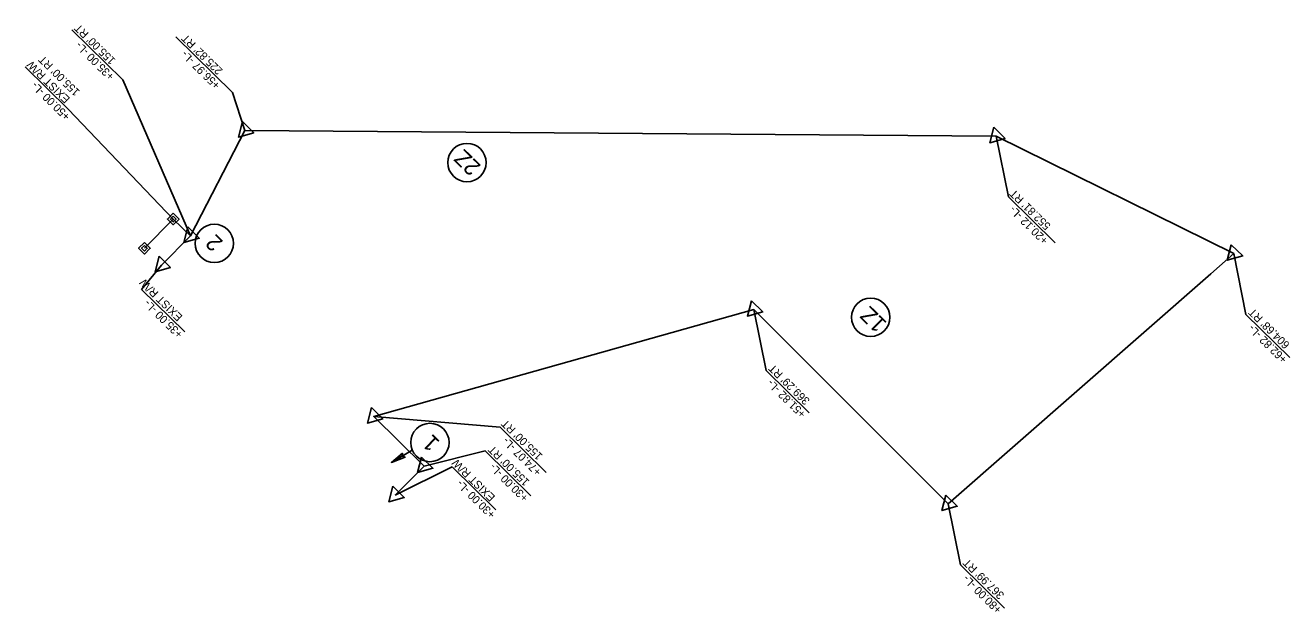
# Model space of a CAD drawing. Extents: x 1266020 to 1268272, y 771352 to 772865.
# Drawn here: x 1267482 to 1268272, y 771352 to 771719 of the extents above; entities that cross this region are included whole.
import ezdxf

# ---------------------------------------------------------------- set-up
doc = ezdxf.new("R2010")
doc.units = 0
for name, color, linetype in [('Prop Dimension Text', 7, 'Continuous'), ('Prop Easement Permanent Drainage', 7, 'Continuous'), ('Prop Easement Permanent Drainage Station Offsets', 7, 'Continuous'), ('Prop Parcel Number CELL', 7, 'Continuous'), ('Prop Parcel Number Text', 7, 'Continuous'), ('Prop ROW Marker CELL', 7, 'Continuous'), ('Prop ROW Permanent Easement CELL', 7, 'Continuous'), ('Prop ROW RW Lines', 7, 'Continuous'), ('Prop ROW Station Offsets', 7, 'Continuous')]:
    doc.layers.add(name, color=color, linetype=linetype)

msp = doc.modelspace()

# ---------------------------------------------------------------- linework, layer by layer
at = {"layer": 'Prop Dimension Text'}
msp.add_lwpolyline([(1267717.81, 771451.44), (1267710.87, 771445.51), (1267719.46, 771448.75), (1267717.66, 771449.54)], close=True, dxfattribs=at)
at = {"layer": 'Prop Easement Permanent Drainage'}
msp.add_lwpolyline([(1267585.27, 771587.19), (1267574.58, 771597.72), (1267556.57, 771579.44)], dxfattribs=at)
at = {"layer": 'Prop Easement Permanent Drainage Station Offsets'}
for p, q in [((1267482.14, 771692.95), (1267509.22, 771666.27)), ((1267509.22, 771666.27), (1267574.58, 771597.72))]:
    msp.add_line(p, q, dxfattribs=at)
at = {"layer": 'Prop Parcel Number CELL'}
for p, q in [((1267758.1, 771633.03), (1267758.1, 771633.03)), ((1267600.22, 771582.5), (1267600.22, 771582.5)), ((1268010.38, 771536.27), (1268010.38, 771536.27)), ((1267723.94, 771453.27), (1267710.87, 771445.51)), ((1267734.96, 771458.02), (1267734.96, 771458.02))]:
    msp.add_line(p, q, dxfattribs=at)
for centre in [(1267758.1, 771633.03), (1267600.22, 771582.5), (1268010.38, 771536.27), (1267734.96, 771458.02)]:
    msp.add_circle(centre, 12, dxfattribs=at)
at = {"layer": 'Prop ROW Marker CELL'}
for p, q in [((1267619.32, 771653.06), (1267619.32, 771653.06)), ((1268088.77, 771649.56), (1268088.77, 771649.56)), ((1267585.27, 771587.19), (1267585.27, 771587.19)), ((1268237.22, 771576.11), (1268237.22, 771576.11)), ((1267567.26, 771568.92), (1267567.26, 771568.92)), ((1267937.38, 771541.08), (1267937.38, 771541.08)), ((1267699.9, 771474.24), (1267699.9, 771474.24)), ((1267731.29, 771443.31), (1267731.29, 771443.31)), ((1267713.31, 771425.06), (1267713.31, 771425.06)), ((1268058.86, 771419.57), (1268058.86, 771419.57))]:
    msp.add_line(p, q, dxfattribs=at)
for points in [[(1267617.78, 771658.62), (1267624.9, 771651.63), (1267615.29, 771648.94)], [(1268087.23, 771655.12), (1268094.35, 771648.12), (1268084.73, 771645.43)], [(1267583.72, 771592.75), (1267590.84, 771585.75), (1267581.23, 771583.07)], [(1268235.68, 771581.67), (1268242.8, 771574.67), (1268233.18, 771571.99)], [(1267565.72, 771574.48), (1267572.84, 771567.48), (1267563.23, 771564.79)], [(1267935.84, 771546.64), (1267942.96, 771539.65), (1267933.34, 771536.96)], [(1267698.36, 771479.8), (1267705.48, 771472.8), (1267695.87, 771470.11)], [(1267729.75, 771448.87), (1267736.87, 771441.87), (1267727.26, 771439.19)], [(1267711.77, 771430.62), (1267718.89, 771423.62), (1267709.27, 771420.94)], [(1268057.32, 771425.13), (1268064.44, 771418.13), (1268054.82, 771415.44)]]:
    msp.add_lwpolyline(points, close=True, dxfattribs=at)
at = {"layer": 'Prop ROW Permanent Easement CELL'}
for p, q in [((1267574.58, 771597.72), (1267574.58, 771597.72)), ((1267556.57, 771579.44), (1267556.57, 771579.44))]:
    msp.add_line(p, q, dxfattribs=at)
for points in [[(1267574.58, 771601.32), (1267578.18, 771597.72), (1267574.58, 771594.12), (1267570.98, 771597.72)], [(1267574.58, 771599.52), (1267576.38, 771597.72), (1267574.58, 771595.92), (1267572.78, 771597.72)], [(1267556.57, 771583.04), (1267560.17, 771579.44), (1267556.57, 771575.84), (1267552.97, 771579.44)], [(1267556.57, 771581.24), (1267558.37, 771579.44), (1267556.57, 771577.64), (1267554.77, 771579.44)]]:
    msp.add_lwpolyline(points, close=True, dxfattribs=at)
at = {"layer": 'Prop ROW RW Lines'}
msp.add_lwpolyline([(1267713.31, 771425.06), (1267731.29, 771443.31), (1267699.9, 771474.24), (1267937.38, 771541.08), (1268058.86, 771419.57), (1268222.84, 771563.49), (1268237.22, 771576.11), (1268088.77, 771649.56), (1267619.32, 771653.06), (1267585.27, 771587.19), (1267567.26, 771568.92)], dxfattribs=at)
at = {"layer": 'Prop ROW Station Offsets'}
for p, q in [((1267511.3, 771715.95), (1267543.05, 771684.66)), ((1267576.3, 771711.6), (1267611.52, 771676.9)), ((1267543.05, 771684.66), (1267585.27, 771587.19)), ((1267611.52, 771676.9), (1267619.32, 771653.06)), ((1268096.37, 771611.53), (1268125.59, 771582.74)), ((1267554.85, 771553.72), (1267581.84, 771527.13)), ((1268244.82, 771538.08), (1268272.17, 771511.13)), ((1267944.98, 771503.05), (1267971.86, 771476.57)), ((1267778.84, 771467.67), (1267699.9, 771474.24)), ((1267778.84, 771467.67), (1267807.66, 771439.27)), ((1267769.57, 771452.7), (1267731.29, 771443.31)), ((1267769.57, 771452.7), (1267798.03, 771424.66)), ((1267748.81, 771442.88), (1267713.31, 771425.06)), ((1267748.81, 771442.88), (1267776.2, 771415.9)), ((1268066.46, 771381.53), (1268093.88, 771354.51))]:
    msp.add_line(p, q, dxfattribs=at)
for points in [[(1268096.37, 771611.53), (1268088.77, 771649.56)], [(1268244.82, 771538.08), (1268237.22, 771576.11)], [(1267554.85, 771553.72), (1267567.26, 771568.92)], [(1267944.98, 771503.05), (1267937.38, 771541.08)], [(1268066.46, 771381.53), (1268058.86, 771419.57)]]:
    msp.add_lwpolyline(points, dxfattribs=at)

# ---------------------------------------------------------------- texts
at = {"layer": 'Prop Easement Permanent Drainage Station Offsets'}
for s, p in [('EXIST R/W', (1267510.44, 771673.1)), ("155.00' RT", (1267516.6, 771677.56)), ('+50.00 -L-', (1267510.64, 771662.38))]:
    msp.add_text(s, height=5, rotation=135.42387, dxfattribs=at).set_placement(p)
at = {"layer": 'Prop Parcel Number Text'}
for s, p in [('2Z', (1267767.29, 771631)), ('2', (1267606.23, 771583.6)), ('1Z', (1268020.93, 771532.89)), ('1', (1267741.68, 771458.41))]:
    msp.add_text(s, height=10, rotation=135.42387, dxfattribs=at).set_placement(p)
at = {"layer": 'Prop ROW Station Offsets'}
for s, p in [("155.00' RT", (1267538.91, 771697.25)), ("225.82' RT", (1267605.86, 771690.89)), ('+35.00 -L-', (1267538.21, 771687.41)), ('+56.97 -L-', (1267604.31, 771681.89)), ("552.81' RT", (1268123.23, 771593.83)), ('+20.12 -L-', (1268121.68, 771584.83)), ('EXIST R/W', (1267580.82, 771536.91)), ('+35.00 -L-', (1267581.02, 771526.18)), ("604.68' RT", (1268272.54, 771519.54)), ('+62.82 -L-', (1268270.99, 771510.54)), ("369.29' RT", (1267972.7, 771484.52)), ('+51.82 -L-', (1267970.29, 771476.36)), ("155.00' RT", (1267805.7, 771449.97)), ('+74.07 -L-', (1267805, 771440.13)), ("155.00' RT", (1267797.54, 771433.73)), ('EXIST R/W', (1267776.07, 771424.2)), ('+30.00 -L-', (1267796.84, 771423.89)), ('+30.00 -L-', (1267776.27, 771413.47)), ("367.99' RT", (1268094.18, 771363)), ('+80.00 -L-', (1268092.63, 771354))]:
    msp.add_text(s, height=5, rotation=135.42387, dxfattribs=at).set_placement(p)

doc.saveas('drawing.dxf')
